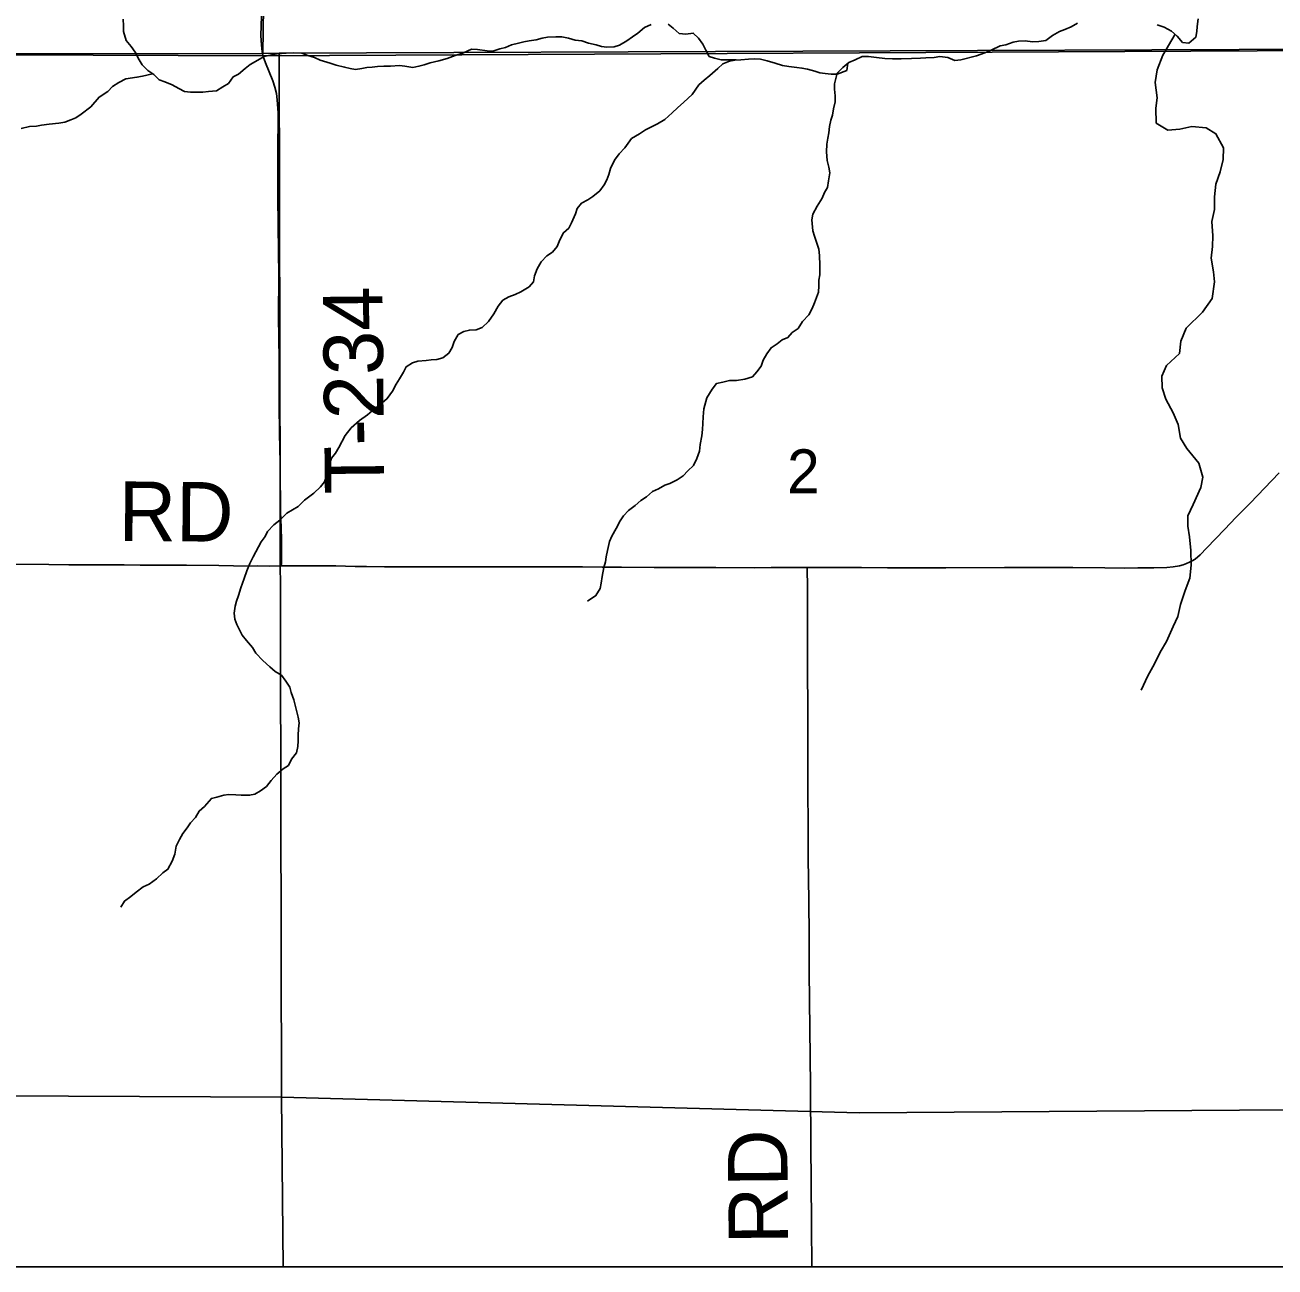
# Model space of a CAD drawing. Extents: x 0 to 34, y 0 to 22.
# Drawn here: x 3.5 to 4.694, y 14.1 to 15.287 of the extents above; entities that cross this region are included whole.
import ezdxf

# ---------------------------------------------------------------- set-up
doc = ezdxf.new("R2010")
doc.units = 0
for name, color, linetype in [('GM_X_County_Road', 7, 'Continuous'), ('GM_X_County_Road_Text', 7, 'Continuous'), ('GM_X_Minor_River', 7, 'Continuous'), ('GM_X_Section', 7, 'Continuous'), ('GM_X_Section_Text', 7, 'Continuous'), ('GM_X_Township_Road', 7, 'Continuous'), ('GM_X_Township_Road_Text', 7, 'Continuous'), ('GM_X_Unincorporated', 7, 'Continuous'), ('SH_Data', 7, 'Continuous')]:
    doc.layers.add(name, color=color, linetype=linetype)

msp = doc.modelspace()

# ---------------------------------------------------------------- linework, layer by layer
at = {"layer": 'GM_X_County_Road'}
for points in [[(4.2468, 14.7682), (4.2769, 14.7684), (4.2986, 14.7683), (4.3235, 14.7681), (4.3478, 14.7681), (4.3794, 14.7681), (4.4353, 14.7683), (4.4664, 14.7682), (4.5006, 14.7682), (4.5312, 14.7679), (4.5503, 14.7678), (4.5627, 14.768), (4.5779, 14.7679), (4.5906, 14.7684), (4.5965, 14.7689), (4.6025, 14.77), (4.6061, 14.7709), (4.6094, 14.7722), (4.6121, 14.7734), (4.6148, 14.7747), (4.6175, 14.7764), (4.6222, 14.7804), (4.6288, 14.787), (4.6455, 14.8047), (4.6567, 14.8164), (4.67, 14.8297), (4.6979, 14.8587)], [(3.48, 14.7716), (3.5224, 14.7711), (3.5414, 14.7708), (3.5654, 14.7707), (3.5942, 14.7707), (3.6096, 14.7705), (3.6313, 14.7705), (3.654, 14.7705), (3.6849, 14.7701), (3.7128, 14.7696), (3.7221, 14.7698), (3.7336, 14.7696), (3.7444, 14.7698)], [(3.7444, 14.7698), (3.7455, 14.7698), (3.7656, 14.77), (3.772, 14.7699), (3.7836, 14.7699), (3.7964, 14.7698), (3.8057, 14.7697), (3.815, 14.7692), (3.8258, 14.7692), (3.8429, 14.7689), (3.8677, 14.7688), (3.8832, 14.7689), (3.8988, 14.7689), (3.9298, 14.769), (3.9733, 14.7689), (4.0106, 14.7689), (4.0323, 14.7688), (4.0509, 14.7686), (4.0696, 14.7685), (4.1007, 14.7683), (4.1348, 14.7684), (4.1597, 14.7683), (4.1969, 14.7681), (4.2124, 14.7682), (4.2335, 14.7682), (4.2468, 14.7682)], [(4.2513, 14.1), (4.2509, 14.1396), (4.2506, 14.1832), (4.2505, 14.2142), (4.2499, 14.2732), (4.2489, 14.3819), (4.2486, 14.4161), (4.2484, 14.4502), (4.2478, 14.4906), (4.2478, 14.5123), (4.2476, 14.565), (4.2475, 14.5898), (4.2476, 14.6302), (4.2473, 14.6737), (4.2471, 14.7234), (4.2471, 14.7482), (4.2468, 14.7682)]]:
    msp.add_lwpolyline(points, dxfattribs=at)
at = {"layer": 'GM_X_Minor_River'}
for points in [[(4.0979, 15.287), (4.0914, 15.2844), (4.085, 15.279), (4.08, 15.2752), (4.0747, 15.2714), (4.0674, 15.2673), (4.0625, 15.2658), (4.0556, 15.2654), (4.0503, 15.2661), (4.0453, 15.2677), (4.038, 15.2692), (4.0315, 15.2715), (4.0251, 15.2722), (4.0189, 15.2741), (4.0125, 15.2753), (4.0067, 15.2753), (3.9987, 15.2749), (3.9938, 15.2742), (3.988, 15.2726), (3.9812, 15.2715), (3.9762, 15.2707), (3.9709, 15.2692), (3.9644, 15.2677), (3.9587, 15.2651), (3.9533, 15.2639), (3.9465, 15.2616), (3.9411, 15.262), (3.932, 15.2632), (3.9262, 15.2635), (3.9186, 15.2601), (3.9106, 15.2575), (3.903, 15.2548), (3.895, 15.2525), (3.8866, 15.2506), (3.8809, 15.2487), (3.8759, 15.2472), (3.8702, 15.2461), (3.8625, 15.2472), (3.8572, 15.248), (3.8488, 15.2472), (3.8423, 15.2472), (3.8362, 15.2469), (3.8313, 15.2465), (3.8263, 15.2461), (3.8213, 15.245), (3.8152, 15.2442), (3.8103, 15.245), (3.8049, 15.2465), (3.7969, 15.2484), (3.7912, 15.2503), (3.7816, 15.253), (3.7763, 15.2556), (3.7698, 15.2575), (3.7641, 15.2598), (3.756, 15.2602), (3.7492, 15.2598), (3.7404, 15.2591), (3.7351, 15.2583), (3.7282, 15.2564), (3.7198, 15.2519), (3.7148, 15.2488), (3.7099, 15.245), (3.7034, 15.2397), (3.6985, 15.2371), (3.6939, 15.2306), (3.6886, 15.2276), (3.6825, 15.2238), (3.6748, 15.223), (3.6695, 15.2226), (3.6577, 15.2226), (3.6519, 15.223), (3.6466, 15.2261), (3.6401, 15.2295), (3.6332, 15.2325), (3.6279, 15.2344), (3.6225, 15.2394), (3.6168, 15.2432), (3.6114, 15.2485), (3.6087, 15.2535), (3.6049, 15.2607), (3.6011, 15.266), (3.5961, 15.2717), (3.5938, 15.2805), (3.5938, 15.2858), (3.5934, 15.2923)], [(4.1789, 15.2532), (4.1789, 15.2535), (4.1648, 15.2535), (4.1583, 15.2551), (4.1533, 15.2566), (4.1499, 15.2627), (4.1472, 15.2684), (4.143, 15.2741), (4.138, 15.279), (4.1308, 15.2779), (4.1246, 15.2786), (4.1189, 15.2836), (4.1139, 15.2874)], [(4.5051, 15.2883), (4.499, 15.2849), (4.4929, 15.2822), (4.488, 15.2803), (4.4811, 15.2765), (4.475, 15.272), (4.4681, 15.2708), (4.462, 15.2705), (4.4552, 15.2716), (4.4487, 15.2712), (4.4437, 15.2701), (4.4368, 15.2678), (4.4311, 15.2667), (4.4227, 15.2625), (4.4166, 15.2599), (4.4086, 15.2572), (4.3938, 15.2534), (4.388, 15.2526), (4.3812, 15.2557), (4.3735, 15.2565), (4.3682, 15.2557), (4.3602, 15.2553), (4.3552, 15.2549), (4.3464, 15.2546), (4.3365, 15.2542), (4.3285, 15.2542), (4.3209, 15.2546), (4.3132, 15.2557), (4.3056, 15.2565), (4.2995, 15.2565), (4.2926, 15.2535), (4.2865, 15.2508), (4.2808, 15.2462), (4.2755, 15.2405), (4.2728, 15.2303), (4.2728, 15.2253), (4.2736, 15.2189), (4.2736, 15.2132), (4.2721, 15.2067), (4.271, 15.2006), (4.2695, 15.1957), (4.2683, 15.1896), (4.2676, 15.1835), (4.2665, 15.1786), (4.2657, 15.1729), (4.2654, 15.1656), (4.2658, 15.1573), (4.2677, 15.1508), (4.2685, 15.1455), (4.2673, 15.1379), (4.2662, 15.1314)], [(4.6203, 15.2924), (4.6196, 15.2852), (4.6192, 15.2803), (4.6181, 15.2749), (4.6116, 15.2693), (4.6055, 15.27), (4.6005, 15.2761), (4.5948, 15.2807), (4.5879, 15.2845), (4.5811, 15.2868)], [(4.5984, 15.2778), (4.5867, 15.2578), (4.5811, 15.2437), (4.5792, 15.2316), (4.5812, 15.2172), (4.5801, 15.2073), (4.5802, 15.1929), (4.5915, 15.1861), (4.6029, 15.1872), (4.6143, 15.1896), (4.6279, 15.1885), (4.6374, 15.1828), (4.6446, 15.1692), (4.6443, 15.1582), (4.6413, 15.1464), (4.6372, 15.1346), (4.6361, 15.1225), (4.6361, 15.1103), (4.6335, 15.0989), (4.6343, 15.0853), (4.634, 15.075), (4.6329, 15.064), (4.6352, 15.0507), (4.636, 15.0412), (4.6338, 15.0253), (4.6244, 15.0123), (4.6089, 14.9971), (4.6037, 14.9846), (4.6026, 14.9728), (4.5901, 14.9614), (4.5856, 14.9511), (4.586, 14.9401), (4.5895, 14.9291), (4.5964, 14.9162), (4.6013, 14.9049), (4.6036, 14.892), (4.6097, 14.8821), (4.6212, 14.8681), (4.625, 14.8545), (4.6231, 14.8446), (4.6156, 14.8286), (4.6104, 14.8176), (4.6104, 14.8077), (4.612, 14.7975), (4.6135, 14.7846), (4.6136, 14.7706), (4.6125, 14.758), (4.608, 14.7462), (4.6035, 14.7329), (4.6009, 14.7216), (4.5964, 14.712), (4.59, 14.6976), (4.584, 14.6873), (4.5787, 14.6763), (4.5723, 14.6649), (4.5659, 14.6512)], [(4.2857, 15.2501), (4.2846, 15.2432), (4.2755, 15.2398), (4.2698, 15.2398), (4.264, 15.2402), (4.2591, 15.2409), (4.2541, 15.2424), (4.2472, 15.2444), (4.2419, 15.2455), (4.2369, 15.2459), (4.2293, 15.247), (4.2232, 15.2478), (4.2163, 15.2501), (4.2087, 15.2524), (4.2022, 15.2539), (4.1965, 15.2543), (4.1907, 15.2539), (4.1835, 15.2535), (4.1778, 15.2531), (4.1728, 15.252), (4.1663, 15.2497), (4.1614, 15.2452), (4.1537, 15.2383), (4.1484, 15.2338), (4.1435, 15.2296), (4.137, 15.2201), (4.129, 15.2129), (4.1229, 15.2075), (4.118, 15.2026), (4.1107, 15.1965), (4.1039, 15.1923), (4.0989, 15.1897), (4.0924, 15.1866), (4.0867, 15.1828), (4.0791, 15.1783), (4.0726, 15.1692), (4.0673, 15.1635), (4.0627, 15.1574), (4.0589, 15.1494), (4.0574, 15.1437), (4.0555, 15.1387), (4.0529, 15.1338), (4.0487, 15.1281), (4.0422, 15.1228), (4.0372, 15.1197), (4.0312, 15.1163), (4.027, 15.1114), (4.0255, 15.1061), (4.0217, 15.0977), (4.019, 15.0924), (4.014, 15.0882), (4.0106, 15.0814), (4.008, 15.0749), (4.0034, 15.0696), (3.9981, 15.0662), (3.9927, 15.0604), (3.9889, 15.0536), (3.9863, 15.0471), (3.9855, 15.0414), (3.9813, 15.0365), (3.9733, 15.0316), (3.968, 15.0293), (3.9619, 15.027), (3.9562, 15.0236), (3.9516, 15.0179), (3.9474, 15.0107), (3.9425, 15.0034), (3.9364, 14.9977), (3.9307, 14.9955), (3.9242, 14.9951), (3.9189, 14.9939), (3.9135, 14.9909), (3.9097, 14.9841), (3.9078, 14.9784), (3.9044, 14.973), (3.8987, 14.9685), (3.893, 14.967), (3.8876, 14.9666), (3.8827, 14.9662), (3.875, 14.9655), (3.8697, 14.9639), (3.8636, 14.9601), (3.8613, 14.9548), (3.8575, 14.9487), (3.8541, 14.9434), (3.8507, 14.9369), (3.8457, 14.9297), (3.8385, 14.9236), (3.8336, 14.9198), (3.8267, 14.9141), (3.8191, 14.9088), (3.8111, 14.9016), (3.8054, 14.8944), (3.7993, 14.883), (3.7963, 14.8777), (3.7924, 14.8727), (3.7906, 14.867), (3.789, 14.8605), (3.7875, 14.8556), (3.7856, 14.8503), (3.7818, 14.8453)], [(3.6214, 15.2401), (3.6118, 15.2379), (3.6065, 15.2367), (3.5958, 15.2352), (3.5893, 15.2318), (3.5832, 15.228), (3.5787, 15.2231), (3.5703, 15.2177), (3.5623, 15.2086), (3.5532, 15.2014), (3.5482, 15.198), (3.5432, 15.1961), (3.5375, 15.1938), (3.5318, 15.1927), (3.5226, 15.1919), (3.5154, 15.1911), (3.5104, 15.19), (3.5039, 15.1896), (3.4959, 15.1877)], [(4.2662, 15.1314), (4.2635, 15.1265), (4.2613, 15.1211), (4.2563, 15.1135), (4.2521, 15.1059), (4.2514, 15.1006), (4.2522, 15.09), (4.2537, 15.085), (4.256, 15.0782), (4.2579, 15.0725), (4.2587, 15.0664), (4.2591, 15.0573), (4.2588, 15.0478), (4.258, 15.0428), (4.258, 15.0375), (4.2577, 15.0314), (4.2539, 15.0211), (4.2516, 15.0158), (4.2485, 15.0097), (4.2425, 15.0033), (4.2383, 14.9968), (4.2326, 14.993), (4.2284, 14.9881), (4.223, 14.9858), (4.2181, 14.982), (4.2124, 14.9782), (4.2082, 14.9725), (4.2048, 14.9664), (4.2029, 14.9607), (4.1987, 14.9554), (4.1945, 14.9504), (4.1873, 14.9482), (4.1792, 14.947), (4.1728, 14.947), (4.1663, 14.9455), (4.1602, 14.944), (4.156, 14.9387), (4.151, 14.9303), (4.148, 14.92), (4.1476, 14.9124), (4.1473, 14.906), (4.1469, 14.9003), (4.1462, 14.8942), (4.1447, 14.8858), (4.1439, 14.8794), (4.1413, 14.8725), (4.1382, 14.8657), (4.1329, 14.8607), (4.1283, 14.8558), (4.1226, 14.852), (4.1157, 14.8486), (4.1108, 14.8471), (4.1047, 14.8436), (4.099, 14.841), (4.0933, 14.8357), (4.0879, 14.8322), (4.0826, 14.8277), (4.0761, 14.8227), (4.0715, 14.8178), (4.0681, 14.8129), (4.0643, 14.8056), (4.0601, 14.7984), (4.0579, 14.7931), (4.056, 14.7847), (4.0548, 14.7786), (4.0541, 14.7737), (4.0526, 14.7684), (4.0511, 14.7596), (4.0499, 14.7532), (4.0492, 14.7482), (4.045, 14.7414), (4.037, 14.7361)], [(3.7818, 14.8453), (3.7754, 14.8393), (3.7666, 14.8328), (3.7605, 14.8267), (3.7498, 14.8203), (3.743, 14.8134), (3.7373, 14.8092), (3.7312, 14.8028), (3.7289, 14.7978), (3.7251, 14.7929), (3.7175, 14.7785), (3.7145, 14.772), (3.7114, 14.7651), (3.7088, 14.7579), (3.7057, 14.7488), (3.7035, 14.7416), (3.7016, 14.7363), (3.7004, 14.7313), (3.6993, 14.7248), (3.7001, 14.7188), (3.702, 14.7138), (3.707, 14.7035), (3.7112, 14.6986), (3.7169, 14.6918), (3.72, 14.6864), (3.7269, 14.6796), (3.7334, 14.6735), (3.7387, 14.6689), (3.7445, 14.6655), (3.7487, 14.6598), (3.7525, 14.6541), (3.754, 14.6488), (3.7564, 14.6419), (3.7579, 14.6355), (3.7606, 14.6252), (3.7614, 14.6199), (3.761, 14.6142), (3.7606, 14.6081), (3.7606, 14.6027), (3.7603, 14.5974), (3.7591, 14.5913), (3.7542, 14.5853), (3.7512, 14.5792), (3.7462, 14.5758), (3.7401, 14.5708), (3.7348, 14.5647), (3.7302, 14.559), (3.7245, 14.5549), (3.7192, 14.5518), (3.7142, 14.5507), (3.7062, 14.5507), (3.7009, 14.5511), (3.6944, 14.5515), (3.6894, 14.5507), (3.6829, 14.5488), (3.6776, 14.5477), (3.6711, 14.5401), (3.6658, 14.5355), (3.6624, 14.5294), (3.6578, 14.5245), (3.6544, 14.5195), (3.6502, 14.5142), (3.6471, 14.5085), (3.6441, 14.502), (3.6426, 14.4944), (3.6403, 14.4876), (3.6361, 14.48), (3.6312, 14.4766), (3.6251, 14.4709), (3.6182, 14.4656), (3.6125, 14.4633), (3.6057, 14.458), (3.6007, 14.4538), (3.5946, 14.4496), (3.5912, 14.4439)]]:
    msp.add_lwpolyline(points, dxfattribs=at)
at = {"layer": 'GM_X_Section'}
for points in [[(2.7146, 16.2714), (3.7413, 16.2718), (3.7269, 15.2595), (2.7116, 15.2583)], [(3.7413, 16.2718), (4.754, 16.2718), (4.743, 15.2637), (3.7425, 15.2596), (3.7269, 15.2595)], [(3.7425, 15.2596), (4.743, 15.2637), (4.7506, 14.2503), (4.2965, 14.2473), (3.7447, 14.2621)], [(3.7269, 15.2595), (3.7425, 15.2596), (3.7447, 14.2621), (2.727, 14.267), (2.7116, 15.2583)]]:
    msp.add_lwpolyline(points, close=True, dxfattribs=at)
at = {"layer": 'GM_X_Township_Road'}
for points in [[(2.1, 20.9), (2.1, 15.2557), (2.7077, 15.2596), (2.915, 15.2604), (3.727, 15.2572), (4.7402, 15.2622)], [(3.7272, 15.2566), (3.7262, 15.2611), (3.7254, 15.2673), (3.725, 15.2766), (3.7254, 15.2952), (3.7255, 15.3014), (3.7255, 15.3106), (3.7255, 15.3261), (3.7253, 15.3821), (3.7256, 15.41), (3.7267, 15.4752), (3.7275, 15.528), (3.728, 15.5653), (3.7286, 15.6057), (3.729, 15.6368), (3.7298, 15.6834), (3.7306, 15.7206), (3.7315, 15.7578), (3.7321, 15.7827), (3.7326, 15.7982), (3.7335, 15.8261), (3.7337, 15.8479), (3.7337, 15.8631)], [(4.7402, 15.2622), (3.727, 15.2572), (2.915, 15.2604), (2.7077, 15.2596), (2.1, 15.2557), (2.1, 14.1), (5.7705, 14.1)], [(3.7444, 14.7698), (3.7445, 14.7717), (3.7446, 14.7848), (3.7445, 14.794), (3.7442, 14.8064), (3.7438, 14.8219), (3.7437, 14.8343), (3.7435, 14.8498), (3.7433, 14.8683), (3.7428, 14.8962), (3.7425, 14.9241), (3.7424, 14.9427), (3.7423, 14.9675), (3.7419, 15.0078), (3.7421, 15.048), (3.7419, 15.0697), (3.7412, 15.1223), (3.741, 15.1564), (3.7411, 15.1749), (3.7415, 15.1905), (3.7414, 15.2028), (3.7406, 15.2152), (3.7398, 15.2213), (3.7383, 15.2273), (3.7363, 15.2332), (3.7292, 15.2504), (3.7272, 15.2566)]]:
    msp.add_lwpolyline(points, dxfattribs=at)
at = {"layer": 'GM_X_Unincorporated'}
for points in [[(2.7279, 14.1), (3.7463, 14.1), (3.7447, 14.2621), (2.727, 14.267)], [(3.7463, 14.1), (4.7523, 14.1), (4.7506, 14.2503), (4.2965, 14.2473), (3.7447, 14.2621)]]:
    msp.add_lwpolyline(points, close=True, dxfattribs=at)
at = {"layer": 'SH_Data'}
msp.add_line((2.1, 14.1), (8.9, 14.1), dxfattribs=at)

# ---------------------------------------------------------------- texts
at = {"layer": 'GM_X_County_Road_Text'}
for rotation, p in [(359.5091, (3.5888, 14.7938)), (90.4991, (4.2287, 14.1219))]:
    msp.add_text('RD', height=0.05682, rotation=rotation, dxfattribs=at).set_placement(p)
at = {"layer": 'GM_X_Section_Text'}
msp.add_text('2', height=0.0419, rotation=0, dxfattribs=at).set_placement((4.2277, 14.8393))
at = {"layer": 'GM_X_Township_Road_Text'}
msp.add_text('T-234', height=0.05682, rotation=90.5573, dxfattribs=at).set_placement((3.8429, 14.8385))

doc.saveas('drawing.dxf')
